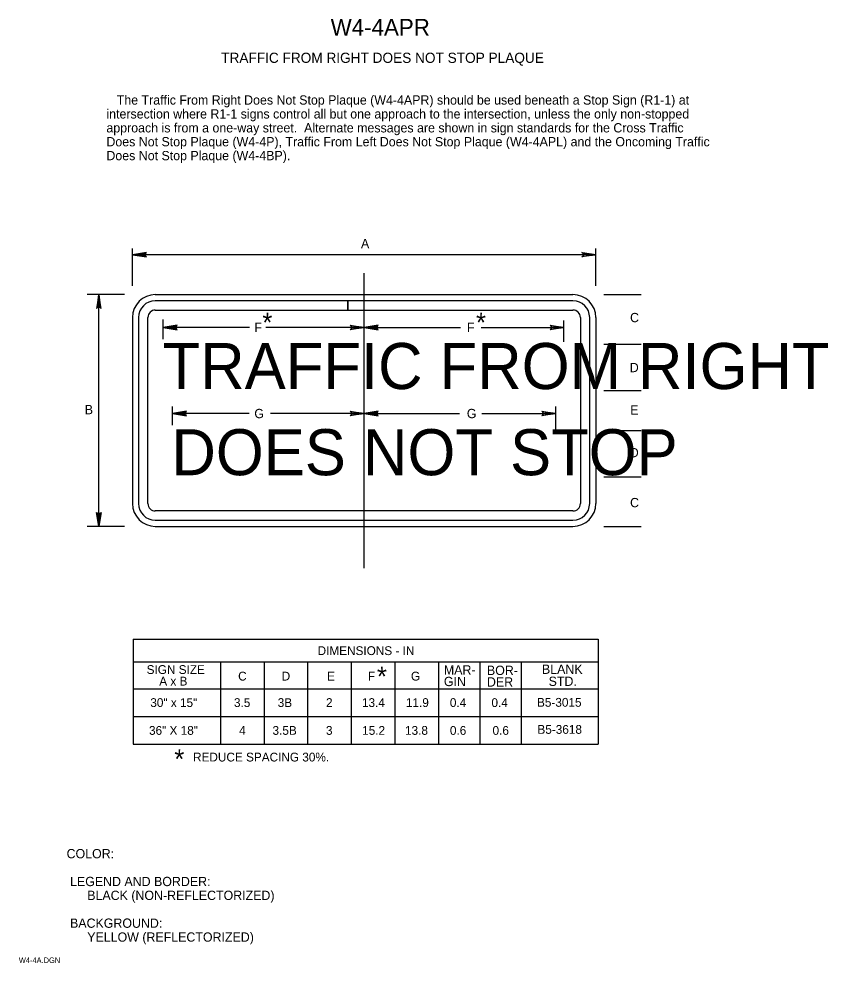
# Model space of a CAD drawing. Extents: x 0.013 to 0.231, y 0.004 to 0.259.
import ezdxf

# ---------------------------------------------------------------- set-up
doc = ezdxf.new("R2010")
doc.units = 0
for name, color, linetype in [('1', 7, 'Continuous'), ('2', 7, 'Continuous'), ('3', 7, 'Continuous')]:
    doc.layers.add(name, color=color, linetype=linetype)

# ---------------------------------------------------------------- blocks, each defined once
blk = doc.blocks.new('RARROW')
at = {"layer": '3'}
for p, q in [((-2.156, 0.285), (-2.2665, 0.384625)), ((-2.2665, 0.384625), (0, 0)), ((0, 0), (-2.2665, -0.379125)), ((-2.156, 0.285), (-2.075625, 0.12075)), ((0, 0), (-2.156, 0.285)), ((-2.14975, -0.2705), (0, 0)), ((-2.075625, 0.12075), (0, 0)), ((0, 0), (-2.074, -0.108)), ((-2.2665, -0.379125), (-2.14975, -0.2705)), ((-2.074, -0.108), (-2.14975, -0.2705))]:
    blk.add_line(p, q, dxfattribs=at)

msp = doc.modelspace()

# ---------------------------------------------------------------- linework, layer by layer
at = {"layer": '1'}
for p, q in [((0.10565, 0.11086), (0.10565, 0.19039)), ((0.0341, 0.12213), (0.0341, 0.18463)), ((0.10127, 0.18297), (0.04931, 0.18297)), ((0.10127, 0.18047), (0.10127, 0.18297)), ((0.16198, 0.18297), (0.10127, 0.18297)), ((0.10127, 0.18297), (0.10127, 0.18047)), ((0.04481, 0.17847), (0.04481, 0.1283)), ((0.04731, 0.1283), (0.04731, 0.17847)), ((0.04931, 0.18047), (0.10127, 0.18047)), ((0.10127, 0.18047), (0.16198, 0.18047)), ((0.16398, 0.17847), (0.16398, 0.1283)), ((0.16648, 0.1283), (0.16648, 0.17847)), ((0.05145, 0.17266), (0.05145, 0.17793)), ((0.10565, 0.17326), (0.10565, 0.17793)), ((0.15955, 0.17194), (0.15955, 0.17769)), ((0.05398, 0.14943), (0.05398, 0.15446)), ((0.10565, 0.15098), (0.10565, 0.1541)), ((0.15731, 0.14823), (0.15731, 0.15446)), ((0.16198, 0.1263), (0.04931, 0.1263)), ((0.04931, 0.1238), (0.16198, 0.1238))]:
    msp.add_line(p, q, dxfattribs=at)
for centre, radius, start, end in [((0.04931, 0.17847), 0.00617, 90, 180), ((0.16198, 0.17847), 0.00617, 360, 90), ((0.04931, 0.17847), 0.0045, 90, 180), ((0.16198, 0.17847), 0.0045, 0, 90), ((0.04931, 0.17847), 0.002, 90, 180), ((0.16198, 0.17847), 0.002, 0, 90), ((0.04931, 0.1283), 0.00617, 180, 270), ((0.04931, 0.1283), 0.0045, 180, 270), ((0.04931, 0.1283), 0.002, 180, 270), ((0.16198, 0.1283), 0.00617, 270, 0), ((0.16198, 0.1283), 0.0045, 270, 0), ((0.16198, 0.1283), 0.002, 270, 0)]:
    msp.add_arc(centre, radius, start, end, dxfattribs=at)
at = {"layer": '3'}
for p, q in [((0.04315, 0.18704), (0.04315, 0.1971)), ((0.16815, 0.18704), (0.16815, 0.1971)), ((0.16815, 0.19541), (0.04315, 0.19541)), ((0.04098, 0.18463), (0.03092, 0.18463)), ((0.04931, 0.18463), (0.16198, 0.18463)), ((0.17031, 0.18463), (0.18037, 0.18463)), ((0.04315, 0.17847), (0.04315, 0.1283)), ((0.16815, 0.17847), (0.16815, 0.1283)), ((0.0747, 0.17577), (0.05145, 0.17577)), ((0.10565, 0.17577), (0.07912, 0.17577)), ((0.10565, 0.17577), (0.13163, 0.17577)), ((0.13723, 0.17577), (0.15873, 0.17577)), ((0.17031, 0.1713), (0.18037, 0.1713)), ((0.17031, 0.1588), (0.18037, 0.1588)), ((0.07461, 0.15254), (0.05398, 0.15254)), ((0.10565, 0.15254), (0.08036, 0.15254)), ((0.10565, 0.15254), (0.13138, 0.15254)), ((0.13737, 0.15254), (0.15731, 0.15254)), ((0.17031, 0.14796), (0.18037, 0.14796)), ((0.17031, 0.13546), (0.18037, 0.13546)), ((0.04098, 0.12213), (0.03092, 0.12213)), ((0.04931, 0.12213), (0.16198, 0.12213)), ((0.17031, 0.12213), (0.18037, 0.12213)), ((0.04333, 0.09173), (0.16877, 0.09173)), ((0.04333, 0.09168), (0.04333, 0.06336)), ((0.16877, 0.09173), (0.16877, 0.06336)), ((0.16877, 0.08548), (0.04333, 0.08548)), ((0.0669, 0.08548), (0.0669, 0.06336)), ((0.07865, 0.08543), (0.07865, 0.06336)), ((0.0904, 0.08543), (0.0904, 0.06336)), ((0.10215, 0.08543), (0.10215, 0.06336)), ((0.1139, 0.08543), (0.1139, 0.06336)), ((0.12571, 0.08548), (0.12571, 0.06336)), ((0.13684, 0.08548), (0.13684, 0.06336)), ((0.14796, 0.08548), (0.14796, 0.06336)), ((0.04333, 0.07836), (0.16877, 0.07836)), ((0.04333, 0.07086), (0.16877, 0.07086)), ((0.04333, 0.06336), (0.16877, 0.06336))]:
    msp.add_line(p, q, dxfattribs=at)

# ---------------------------------------------------------------- block references
at = {"layer": '3', "xscale": 0.0016545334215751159}
for p, yscale, rotation in [((0.04315, 0.19541), -0.0016366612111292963, -180), ((0.0341, 0.18463), -0.0016366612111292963, 90), ((0.05145, 0.17577), -0.0016366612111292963, -180), ((0.10565, 0.17577), -0.0016366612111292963, -180), ((0.05398, 0.15254), -0.0016366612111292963, -180), ((0.10565, 0.15254), -0.0016366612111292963, -180), ((0.0341, 0.12213), 0.0016366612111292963, -90)]:
    msp.add_blockref('RARROW', p, dxfattribs=dict(at, yscale=yscale, rotation=rotation))
at = {"layer": '3', "xscale": 0.0016545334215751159, "yscale": 0.0016366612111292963}
for p in [(0.16815, 0.19541), (0.10565, 0.17577), (0.15955, 0.17577), (0.10565, 0.15254), (0.15731, 0.15254)]:
    msp.add_blockref('RARROW', p, dxfattribs=at)

# ---------------------------------------------------------------- texts
at = {"layer": '1'}
for s, height, p in [('W4-4APR', 0.0045, (0.09662, 0.2545)), ('TRAFFIC FROM RIGHT DOES NOT STOP PLAQUE', 0.0027503, (0.06708, 0.24713)), ('COLOR:', 0.0025, (0.02538, 0.03262)), (' LEGEND AND BORDER:', 0.0024998, (0.02538, 0.02512)), ('      BLACK (NON-REFLECTORIZED)', 0.0024998, (0.02538, 0.02138)), (' BACKGROUND:', 0.0024998, (0.02538, 0.01388)), ('      YELLOW (REFLECTORIZED)', 0.0024998, (0.02538, 0.01013)), ('W4-4A.DGN', 0.0015, (0.0125, 0.00438))]:
    msp.add_text(s, height=height, dxfattribs=at).set_placement(p)
at = {"layer": '2'}
for s, height, p in [('   The Traffic From Right Does Not Stop Plaque (W4-4APR) should be used beneath a Stop Sign (R1-1) at ', 0.00249975, (0.03612, 0.23588)), ('intersection where R1-1 signs control all but one approach to the intersection, unless the only non-stopped ', 0.00249975, (0.03612, 0.23213)), ('approach is from a one-way street.  Alternate messages are shown in sign standards for the Cross Traffic ', 0.00249975, (0.03612, 0.22838)), ('Does Not Stop Plaque (W4-4P), Traffic From Left Does Not Stop Plaque (W4-4APL) and the Oncoming Traffic ', 0.00249975, (0.03612, 0.22463)), ('Does Not Stop Plaque (W4-4BP).', 0.0024998, (0.03612, 0.22088))]:
    msp.add_text(s, height=height, dxfattribs=at).set_placement(p)
at = {"layer": '3'}
for s, height, p in [('A', 0.0025, (0.10479, 0.19716)), ('*', 0.00518, (0.0782, 0.17455)), ('C', 0.0025, (0.17738, 0.1772)), ('F', 0.0025, (0.13338, 0.17456)), ('TRAFFIC FROM RIGHT', 0.01242, (0.05128, 0.15917)), ('B', 0.0025, (0.03028, 0.15237)), ('G', 0.0025, (0.13334, 0.15132)), ('DOES NOT STOP', 0.01242, (0.05365, 0.13593)), ('DIMENSIONS - IN', 0.0023752, (0.09309, 0.08743)), ('SIGN SIZE', 0.002375, (0.04697, 0.08233)), ('MAR-', 0.0025, (0.12715, 0.08218)), ('BOR-', 0.0025, (0.13877, 0.08206)), ('BLANK', 0.0025, (0.15361, 0.08236)), ('A x B', 0.002375, (0.05038, 0.07921)), ('C', 0.00238, (0.07165, 0.08056)), ('D', 0.00238, (0.0834, 0.08056)), ('E', 0.00238, (0.09565, 0.08056)), ('F', 0.00238, (0.10665, 0.08056)), ('G', 0.00238, (0.11827, 0.08056)), ('GIN', 0.0025, (0.12715, 0.07906)), ('STD.', 0.0025, (0.15541, 0.07911)), ('DER', 0.0025, (0.13877, 0.07893)), ('30" x 15"', 0.002375, (0.04796, 0.07342)), ('3.5', 0.002375, (0.07053, 0.07342)), ('3B', 0.002375, (0.08233, 0.07342)), ('2', 0.00238, (0.09536, 0.07342)), ('13.4', 0.002375, (0.10505, 0.07342)), ('11.9', 0.002375, (0.11691, 0.07342)), ('0.4', 0.002375, (0.12877, 0.07342)), ('B5-3015', 0.002375, (0.15228, 0.07349)), ('36" X 18"', 0.002375, (0.04761, 0.06592)), ('4', 0.00238, (0.07192, 0.06592)), ('3.5B', 0.002375, (0.08093, 0.06592)), ('3', 0.00238, (0.09534, 0.06592)), ('15.2', 0.002375, (0.10511, 0.06592)), ('13.8', 0.002375, (0.11667, 0.06592)), ('0.6', 0.002375, (0.12878, 0.06592)), ('B5-3618', 0.002375, (0.15239, 0.06619)), ('REDUCE SPACING 30%.', 0.0023752, (0.05949, 0.05873))]:
    msp.add_text(s, height=height, dxfattribs=at).set_placement(p)
for s, height, p in [('*', 0.00518, (0.13582, 0.17455)), ('F', 0.0025, (0.07604, 0.17456)), ('D', 0.0025, (0.1773, 0.16372)), ('G', 0.0025, (0.07602, 0.15132)), ('E', 0.0025, (0.17744, 0.15228)), ('D', 0.0025, (0.1773, 0.14078)), ('C', 0.0025, (0.17738, 0.1273)), ('*', 0.00518, (0.10909, 0.0791)), ('0.4', 0.002375, (0.13999, 0.07342)), ('0.6', 0.002375, (0.14028, 0.06592)), ('*', 0.00518, (0.05444, 0.05682))]:
    msp.add_text(s, height=height, rotation=360, dxfattribs=at).set_placement(p)

doc.saveas('drawing.dxf')
